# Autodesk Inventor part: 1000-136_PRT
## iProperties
Created: 2007-03
Part Number: 1000-136_PRT
Document SubType Name: Modeling
Designer: Andy Moles
Material: Steel
Mass: 16.0068 g
Surface Area: 14.8903 cm^2
Volume: 2.03908 cm^3
Density: 7.85 g/cm^3
Author: Andy Moles
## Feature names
1. Base1
